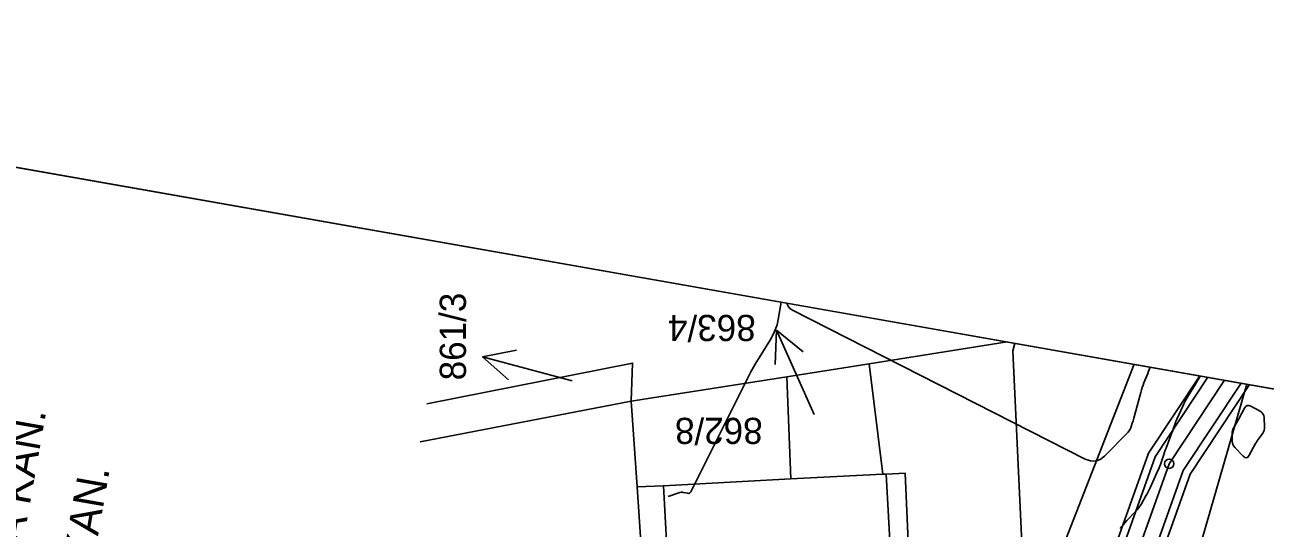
# Model space of a CAD drawing. Extents: x -534481 to -534256, y -1190577 to -1190138.
# Drawn here: x -534381.37 to -534341.14, y -1190154.02 to -1190137.67 of the extents above; entities that cross this region are included whole.
import ezdxf

# ---------------------------------------------------------------- set-up
doc = ezdxf.new("R2010")
doc.units = 0
for name, color, linetype in [('0_kroužky', 7, 'Continuous'), ('30', 7, 'Continuous'), ('31', 7, 'Continuous'), ('_N_osa', 7, 'Continuous'), ('_rámeček', 7, 'Continuous'), ('_rámeček_mřížka', 7, 'Continuous'), ('_tenka', 7, 'Continuous'), ('Hranice parcel', 7, 'Continuous'), ('LEGENDA', 7, 'Continuous'), ('Parcelní čísla', 7, 'Continuous'), ('Polygon budovy', 7, 'Continuous'), ('Pop  PČ popisy', 7, 'Continuous')]:
    doc.layers.add(name, color=color, linetype=linetype)

msp = doc.modelspace()

# ---------------------------------------------------------------- linework, layer by layer
at = {"layer": '0_kroužky'}
msp.add_circle((-534344.257, -1190151.926), 0.15, dxfattribs=at)
msp.add_circle((-534344.257, -1190151.926), 0.15, dxfattribs=at)
msp.add_circle((-534344.257, -1190151.926), 0.15, dxfattribs=at)
msp.add_circle((-534344.257, -1190151.926), 0.15, dxfattribs=at)
msp.add_circle((-534344.257, -1190151.926), 0.15, dxfattribs=at)
msp.add_circle((-534344.257, -1190151.926), 0.15, dxfattribs=at)
at = {"layer": '30'}
for points in [[(-534360.503, -1190152.994), (-534360.156, -1190152.869), (-534360.121, -1190152.859), (-534360.086, -1190152.854), (-534360.051, -1190152.854), (-534360.015, -1190152.859), (-534359.872, -1190152.887), (-534359.838, -1190152.889), (-534359.81, -1190152.881), (-534359.786, -1190152.864), (-534359.767, -1190152.836), (-534357.9, -1190149.097), (-534357.82, -1190148.941), (-534357.736, -1190148.787), (-534357.648, -1190148.635), (-534357.557, -1190148.484), (-534357.185, -1190147.887), (-534357.099, -1190147.735), (-534357.03, -1190147.577), (-534356.975, -1190147.413), (-534356.937, -1190147.243), (-534356.837, -1190146.68)], [(-534356.652, -1190146.713), (-534356.651, -1190146.726), (-534356.617, -1190146.814), (-534356.556, -1190146.887), (-534356.47, -1190146.945), (-534346.982, -1190151.777), (-534346.812, -1190151.837), (-534346.651, -1190151.841), (-534346.5, -1190151.787), (-534346.358, -1190151.677), (-534345.591, -1190150.904), (-534345.563, -1190150.873), (-534345.54, -1190150.84), (-534345.521, -1190150.804), (-534345.506, -1190150.765), (-534345.453, -1190150.607), (-534345.44, -1190150.568), (-534345.428, -1190150.528), (-534345.416, -1190150.488), (-534345.405, -1190150.448), (-534345.179, -1190149.609), (-534345.157, -1190149.53), (-534345.132, -1190149.453), (-534345.105, -1190149.376), (-534345.076, -1190149.299), (-534344.955, -1190148.996), (-534344.925, -1190148.92), (-534344.898, -1190148.843), (-534344.879, -1190148.788)]]:
    msp.add_lwpolyline(points, dxfattribs=at)
msp.add_lwpolyline([(-534341.193, -1190150.364), (-534341.218, -1190150.308), (-534341.257, -1190150.261), (-534341.31, -1190150.224), (-534341.605, -1190150.062), (-534341.67, -1190150.038), (-534341.727, -1190150.04), (-534341.776, -1190150.07), (-534341.817, -1190150.126), (-534341.999, -1190150.473), (-534342.019, -1190150.51), (-534342.04, -1190150.548), (-534342.061, -1190150.586), (-534342.083, -1190150.623), (-534342.171, -1190150.771), (-534342.19, -1190150.808), (-534342.204, -1190150.848), (-534342.211, -1190150.888), (-534342.214, -1190150.931), (-534342.211, -1190151.194), (-534342.205, -1190151.25), (-534342.189, -1190151.303), (-534342.164, -1190151.351), (-534342.129, -1190151.395), (-534341.86, -1190151.677), (-534341.804, -1190151.721), (-534341.752, -1190151.731), (-534341.705, -1190151.708), (-534341.662, -1190151.651), (-534341.455, -1190151.273), (-534341.429, -1190151.228), (-534341.403, -1190151.184), (-534341.374, -1190151.141), (-534341.345, -1190151.098), (-534341.226, -1190150.929), (-534341.2, -1190150.886), (-534341.182, -1190150.84), (-534341.172, -1190150.792), (-534341.17, -1190150.741), (-534341.183, -1190150.429)], close=True, dxfattribs=at)
at = {"layer": '31'}
msp.add_lwpolyline([(-534343.253, -1190149.075), (-534343.29, -1190149.144), (-534343.318, -1190149.193), (-534343.346, -1190149.242), (-534343.374, -1190149.291), (-534343.404, -1190149.34), (-534343.649, -1190149.741), (-534343.695, -1190149.818), (-534343.738, -1190149.897), (-534343.779, -1190149.976), (-534343.817, -1190150.057), (-534344.008, -1190150.476), (-534344.024, -1190150.511), (-534344.039, -1190150.548), (-534344.053, -1190150.584), (-534344.065, -1190150.621), (-534344.115, -1190150.77), (-534344.127, -1190150.807), (-534344.14, -1190150.844), (-534344.154, -1190150.881), (-534344.168, -1190150.918), (-534344.336, -1190151.357), (-534344.361, -1190151.423), (-534344.385, -1190151.489), (-534344.409, -1190151.555), (-534344.431, -1190151.622), (-534344.52, -1190151.889), (-534344.543, -1190151.956), (-534344.568, -1190152.022), (-534344.595, -1190152.087), (-534344.623, -1190152.151), (-534344.877, -1190152.71), (-534344.909, -1190152.777), (-534344.941, -1190152.843), (-534344.976, -1190152.908), (-534345.012, -1190152.972), (-534345.159, -1190153.227), (-534345.198, -1190153.29), (-534345.24, -1190153.35), (-534345.285, -1190153.407), (-534345.334, -1190153.462), (-534345.627, -1190153.774), (-534345.684, -1190153.836), (-534345.74, -1190153.9), (-534345.794, -1190153.964), (-534345.846, -1190154.031)], dxfattribs=at)
at = {"layer": '_N_osa'}
msp.add_lwpolyline([(-534342.428, -1190234.65), (-534342.865, -1190226.62), (-534344.323, -1190207.198), (-534345.257, -1190192.285), (-534345.89, -1190175.458), (-534346.05, -1190156.962), (-534344.257, -1190151.926), (-534342.463, -1190149.215)], dxfattribs=at)
at = {"layer": '_rámeček'}
msp.add_line((-534261.668, -1190163.461), (-534407.912, -1190137.674), dxfattribs=at)
msp.add_lwpolyline([(-534261.668, -1190163.461), (-534407.912, -1190137.674), (-534426.145, -1190241.079), (-534333.072, -1190257.49)], dxfattribs=at)
at = {"layer": '_rámeček_mřížka'}
msp.add_line((-534261.668, -1190163.461), (-534407.912, -1190137.674), dxfattribs=at)
at = {"layer": '_tenka'}
for points in [[(-534343.317, -1190232.109), (-534343.613, -1190226.668), (-534345.072, -1190207.25), (-534346.006, -1190192.323), (-534346.64, -1190175.475), (-534346.801, -1190156.835), (-534344.933, -1190151.588), (-534343.268, -1190149.073)], [(-534343.067, -1190232.098), (-534343.364, -1190226.652), (-534344.822, -1190207.233), (-534345.756, -1190192.31), (-534346.39, -1190175.47), (-534346.551, -1190156.878), (-534344.708, -1190151.701), (-534343, -1190149.12)], [(-534342.068, -1190232.057), (-534342.366, -1190226.587), (-534343.825, -1190207.164), (-534344.757, -1190192.26), (-534345.39, -1190175.446), (-534345.55, -1190157.046), (-534343.807, -1190152.151), (-534341.926, -1190149.309)], [(-534341.818, -1190232.046), (-534342.116, -1190226.571), (-534343.575, -1190207.147), (-534344.507, -1190192.248), (-534345.14, -1190175.441), (-534345.299, -1190157.088), (-534343.581, -1190152.264), (-534341.657, -1190149.357)]]:
    msp.add_lwpolyline(points, dxfattribs=at)
at = {"layer": 'Hranice parcel'}
for p, q in [((-534349.508, -1190147.972), (-534353.99, -1190148.68)), ((-534353.99, -1190148.68), (-534356.66, -1190149.1)), ((-534353.99, -1190148.68), (-534353.54, -1190152.27)), ((-534356.53, -1190152.42), (-534356.66, -1190149.1)), ((-534361.7, -1190149.89), (-534368.546, -1190151.22)), ((-534361.7, -1190149.89), (-534361.51, -1190152.68)), ((-534353.54, -1190152.27), (-534356.53, -1190152.42)), ((-534353.43, -1190152.26), (-534353.54, -1190152.27))]:
    msp.add_line(p, q, dxfattribs=at)
for points in [[(-534349.263, -1190148.015), (-534349.33, -1190148.26), (-534348.67, -1190162.35), (-534348.64, -1190164.35), (-534348.75, -1190166.39), (-534349.02, -1190168.37), (-534349.42, -1190170.33), (-534353.85, -1190185.89), (-534354.6, -1190189.86), (-534354.75, -1190192.89), (-534354.73, -1190197.08)], [(-534368.328, -1190149.982), (-534361.66, -1190148.66), (-534361.7, -1190149.89)], [(-534347.19, -1190196.18), (-534347.17, -1190176.21), (-534348.39, -1190156.38), (-534345.398, -1190148.697)], [(-534356.66, -1190149.1), (-534360.81, -1190149.75), (-534361.7, -1190149.89)], [(-534341.743, -1190149.341), (-534343.82, -1190156.54), (-534343.24, -1190185.5)], [(-534353.43, -1190152.26), (-534352.82, -1190152.23), (-534352.3, -1190164.02), (-534352.41, -1190166), (-534352.72, -1190168), (-534353.15, -1190169.96), (-534355.5, -1190178.16)], [(-534356.53, -1190152.42), (-534360.66, -1190152.64), (-534361.51, -1190152.68)], [(-534356.05, -1190164.42), (-534352.78, -1190164.24), (-534353.43, -1190152.26)], [(-534361.51, -1190152.68), (-534361.14, -1190158.2), (-534360.62, -1190167.61)]]:
    msp.add_lwpolyline(points, dxfattribs=at)
at = {"layer": 'Polygon budovy'}
msp.add_lwpolyline([(-534359.85, -1190167.58), (-534356.61, -1190167.47), (-534356.7, -1190164.46), (-534356.05, -1190164.42), (-534352.78, -1190164.24), (-534353.43, -1190152.26), (-534353.54, -1190152.27), (-534356.53, -1190152.42), (-534360.66, -1190152.64)], close=True, dxfattribs=at)
at = {"layer": 'Pop  PČ popisy'}
for p, q in [((-534356.987, -1190147.586), (-534357.037, -1190148.705)), ((-534355.766, -1190150.328), (-534356.987, -1190147.586)), ((-534356.987, -1190147.586), (-534356.122, -1190148.298)), ((-534366.52, -1190148.459), (-534365.423, -1190148.235)), ((-534363.621, -1190149.236), (-534366.52, -1190148.459)), ((-534366.52, -1190148.459), (-534365.682, -1190149.202))]:
    msp.add_line(p, q, dxfattribs=at)

# ---------------------------------------------------------------- texts
at = {"layer": 'LEGENDA'}
for s, p in [('KANALIZACE - SLOVÁCKÉ VDV A KAN.', (-534384.939, -1190174.445)), ('VODOVOD - SLOVÁCKÉ VDV A KAN.', (-534382.62, -1190174.853))]:
    msp.add_text(s, height=1, rotation=79.9998, dxfattribs=at).set_placement(p)
at = {"layer": 'Parcelní čísla'}
for s, rotation, p in [('861/3', 90, (-534367.061, -1190149.218)), ('863/4', 180, (-534357.665, -1190147.093)), ('862/8', 180, (-534357.44, -1190150.435))]:
    msp.add_text(s, height=0.85, rotation=rotation, dxfattribs=at).set_placement(p)

doc.saveas('drawing.dxf')
